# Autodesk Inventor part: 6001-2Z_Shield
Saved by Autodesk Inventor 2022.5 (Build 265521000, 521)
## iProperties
Created: 2024-12
Part Number: 6001-2Z_Shield
Material: Generic
Document SubType Name: Modeling
Designer: AdminForWorker
Density: 1 g/cm^3
Appearance: Default
Title: 6001-2Z_Shield
Author: AdminForWorker
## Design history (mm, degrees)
feature "Body1"
body "Solid1"
